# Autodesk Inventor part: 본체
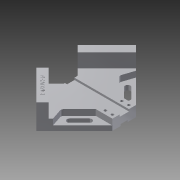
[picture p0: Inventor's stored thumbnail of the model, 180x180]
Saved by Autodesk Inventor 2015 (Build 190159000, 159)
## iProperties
Created: 2019-04
Part Number: 본체
Material: 알루미늄 6061
Document SubType Name: Modeling
Designer: LINEART-SSD.D4.16.04
Density: 2.7 g/cm^3
Appearance: 알루미늄 - 평지
Mass: 608.093 g
Surface Area: 428.235 cm^2
Volume: 225.22 cm^3
Author: LINEART-SSD.D4.16.04
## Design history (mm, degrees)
sketch "스케치1"
  geometry: L1 (-84.853, 0)-(0, -84.853); L2 (0, -84.853)-(84.853, 0); L3 (84.853, 0)-(0, 84.853); L4 (0, 84.853)-(-84.853, 0); L5 (-84.853, 0)-(84.853, 0); L6 (0, -84.853)-(0, 84.853); L7 (-84.853, 0)-(35.147, 0); 1 further point
  constraints: 14 end point, 2 midpoint, 2 parallel, 1 equal length, 1 horizontal, 1 perpendicular
  dimensions: "d0" = 120 distance of L1.start L1.end; "d1" = 45 deg angle of L1 L7; "d2" = 120 distance of L2.end L1.end
extrude "돌출1" new body sketch "스케치1" distance "d3" = 42; taper "d4" = 0 deg
sketch "스케치2"
  geometry: L1 (-84.853, 0)-(0, 84.853); L2 (84.853, 0)-(0, 84.853) reference; L3 (-74.246, -10.607)-(0, 63.64); L4 (0, 63.64)-(74.246, -10.607); L5 (-74.246, -10.607)-(0, -84.853); L6 (-84.853, 0)-(0, -84.853) reference; L7 (0, -84.853)-(74.246, -10.607); 1 further point
  constraints: 10 end point, 3 perpendicular, 1 collinear, 1 other
  dimensions: "d5" = 15 distance between parallel lines of L1 L3
extrude "돌출2" cut sketch "스케치2" distance "d6" = 24; taper "d7" = 0 deg
sketch "스케치3"
  geometry: L1 (0, 84.853)-(-35.355, 49.497); L2 (0, 84.853)-(-84.853, 0) reference; L3 (0, 84.853)-(35.355, 49.497); L4 (84.853, 0)-(0, 84.853) reference; L5 (35.355, 49.497)-(15.47, 29.612); L6 (-11.322, 29.612)-(-33.281, 51.571); L7 (0, -84.853)-(14, -84.853); L8 (0, -64.853)-(14, -64.853); L9 (4.143, 28.147)-(11.934, 28.147); L10 (4.143, 28.147)-(-7.786, 28.147); A1 r 5 centre (-7.786, 33.147) between (-11.322, 29.612) and (-7.786, 28.147); A2 r 5 centre (11.934, 33.147) between (11.934, 28.147) and (15.47, 29.612); 4 further points
  constraints: 16 end point, 9 point on line, 4 point on circle, 4 tangent, 2 centre point, 2 horizontal, 2 parallel, 1 equal radius, 1 perpendicular
  dimensions: "d8" = 50 distance of L1.start L1.end; "d9" = 50 distance of L1.start L3.end; "d12" = 14 distance of L7.start L7.end; "d13" = 20 distance between parallel lines of L7 L8; "d14" = 93 distance between parallel lines of L8 L9; "d16" = 33.12691 distance of point (-9.857, 28.147) L6.end; "d17" = 30.19387 distance of L3.end point (14.005, 28.147); "d18" = 14 distance of L9.start point (-9.857, 28.147); "d19" = 9.85711 distance of L9.start point (14, 28.147); "d20" = 5 radius of A1
extrude "돌출3" cut sketch "스케치3" stored distance "d21" = 0; taper "d22" = 0 deg
sketch "스케치4"
  geometry: L1 (0, -84.853)-(25, -84.853); L2 (-11, -64.853)-(25, -64.853); L3 (-11, -64.853)-(-25, -64.853); L4 (25, -64.853)-(25, -84.853); L5 (0, -84.853)-(-25, -84.853); L6 (-25, -84.853)-(-25, -64.853); 1 further point
  constraints: 12 end point, 3 horizontal, 1 parallel, 1 perpendicular, 1 vertical
  dimensions: "d23" = 25 distance of L1.start L1.end; "d24" = 20 distance between parallel lines of L1 L2; "d25" = 14 distance of L2.start L3.end; "d28" = 25 distance of L1.start L5.end
extrude "돌출4" cut sketch "스케치4" stored distance "d29" = 24; taper "d30" = 0 deg
sketch "스케치6"
  geometry: L1 (-7.786, 28.147)-(8.214, 28.147); L2 (11.934, 28.147)-(-7.786, 28.147) reference; L3 (-7.786, 28.147)-(-7.786, -64.853); L4 (8.214, 28.147)-(8.214, -64.853); L5 (-7.786, -64.853)-(8.214, -64.853); L6 (-20, -64.853)-(20, -64.853) reference; 1 further point
  constraints: 8 end point, 1 collinear, 1 point on line, 1 vertical
  dimensions: "d39" = 16 distance of L1.start L1.end; "d95" = 93 distance of L4.end L1.end; "d96" = 16 distance of L4.end L3.end
extrude "돌출5" cut sketch "스케치6" distance "d43" = 3.5; taper "d44" = 0 deg
sketch "스케치7"
  geometry: L1 (8.214, 64.853)-(-7.786, 64.853) reference; L2 (-6, -28.147)-(-6, 64.853); L3 (-6, 64.853)-(6, 64.853); L4 (6, 64.853)-(6, -28.147); L5 (6, -28.147)-(-7.343, -28.147); L6 (-7.786, -28.147)-(11.934, -28.147) reference; 2 further points
  constraints: 8 end point, 4 point on line, 1 parallel
  dimensions: "d47" = 12 distance of L2.end L3.end; "d48" = 93 distance of L2.start L2.end; "d49" = 93 distance of L3.end L4.end; "d50" = 13.34265 distance of L4.end L5.end; "d51" = 6 distance from line of L4 point (0, 0)
extrude "돌출6" cut sketch "스케치7" distance "d52" = 3; taper "d53" = 0 deg
sketch "스케치8"
  geometry: L1 (-84.853, 0)-(-70.711, -14.142); L2 (-84.853, 0)-(-20, -64.853) reference; L3 (-20, -64.853)-(-20, -36.569); L4 (-47.312, -9.256)-(-20, -36.569) reference; L5 (-70.711, -14.142)-(-20, -64.853); L6 (-84.853, 0)-(-77.782, 7.071); L7 (-33.281, 51.571)-(-84.853, 0) reference; L8 (-77.782, 7.071)-(-49.497, -21.213); L9 (-77.782, 7.071)-(-37.782, 7.071); L10 (-49.497, -21.213)-(-32.527, -38.184); L11 (-6, -64.853)-(6, -64.853) reference; L12 (0, -64.853)-(0, 0); L13 (20, -64.853)-(20, -36.569); L14 (70.711, -14.142)-(20, -64.853); L15 (-84.853, 0)-(-63.64, -21.213); L16 (-70.711, -14.142)-(-52.429, -8.048); L17 (70.711, -14.142)-(52.429, -8.048); L18 (20, -36.569)-(47.312, -9.256); A1 r 5 centre (-50.848, -12.792) between (-47.312, -9.256) and (-52.429, -8.048); A2 r 5 centre (50.848, -12.792) between (52.429, -8.048) and (47.312, -9.256); 3 further points
  constraints: 32 end point, 8 symmetric about line, 4 point on circle, 3 point on line, 2 centre point, 2 midpoint, 2 tangent, 2 vertical, 1 collinear, 1 equal length, 1 horizontal, 1 parallel, 2 other
  dimensions: "d54" = 20 distance of L1.start L1.end; "d57" = 10 distance of L1.start L6.end; "d58" = 40 distance of L6.end L8.end; "d59" = 45 deg angle of L8 L9; "d60" = 24 distance of L8.end L10.end; "d64" = 30 distance of L1.start L15.end; "d65" = 5 radius of A1; "d66" = 19.27051 distance of L1.end L16.end
extrude "돌출7" cut sketch "스케치8" distance "d62" = 10; taper "d63" = 0 deg
sketch "스케치10"
  geometry: L1 (-84.853, 0)-(-77.782, 7.071); L2 (-33.281, 51.571)-(-84.853, 0) reference; L3 (-84.853, 0)-(-74.853, 0); L4 (-77.782, 7.071)-(-49.497, -21.213); L5 (-77.782, 7.071)-(-37.782, 7.071); L6 (-49.497, -21.213)-(-32.527, -38.184); L7 (-52.679, -24.395)-(-35.709, -41.366); L8 (-29.345, -35.002)-(-46.315, -18.031); L9 (8.214, -64.853)-(-7.786, -64.853) reference; L10 (0.107, -64.853)-(0.107, 28.391); L11 (29.559, -35.002)-(46.529, -18.031); L12 (52.893, -24.395)-(35.923, -41.366); L13 (49.711, -21.213)-(32.741, -38.184); A1 r 4.5 centre (-49.497, -21.213) between (-46.315, -18.031) and (-52.679, -24.395); A2 r 4.5 centre (-32.527, -38.184) between (-35.709, -41.366) and (-29.345, -35.002); A3 r 4.5 centre (49.711, -21.213) between (52.893, -24.395) and (46.529, -18.031); A4 r 4.5 centre (32.741, -38.184) between (29.559, -35.002) and (35.923, -41.366); 3 further points
  constraints: 26 end point, 8 point on circle, 6 symmetric about line, 4 centre point, 4 tangent, 2 equal length, 2 horizontal, 1 collinear, 1 midpoint, 1 parallel, 1 point on line, 1 vertical, 2 other
  dimensions: "d67" = 10 distance of L1.start L1.end; "d68" = 45 deg angle of L3 L1 (derived); "d69" = 40 distance of L1.end L4.end; "d70" = 45 deg angle of L4 L5; "d71" = 24 distance of L4.end L6.end; "d72" = 9 diameter of A2; "d73" = 16.97056 horizontal distance of L13.start L13.end
extrude "돌출8" cut sketch "스케치10" stored distance "d74" = 10; taper "d75" = 0 deg
sketch "스케치11"
  geometry: L1 (8.214, -64.853)-(-7.786, -64.853) reference; L2 (0.107, -64.853)-(14.107, -64.853); L3 (20, -64.853)-(6, -64.853) reference; L4 (14.107, -64.853)-(14.107, -58.853); L5 (14.107, -58.853)-(14.107, -46.853); L6 (8, 28.147)-(8, -64.853) reference; L7 (0.107, -64.853)-(0.107, -27.265); C1 r 2.25 at (14.107, -58.853); C2 r 2.25 at (14.107, -46.853); C3 r 2.25 at (-13.893, -46.853); C4 r 2.25 at (-13.893, -58.853); 1 further point
  constraints: 8 end point, 4 centre point, 3 point on line, 2 coincident, 2 symmetric about line, 1 perpendicular, 1 vertical, 2 other
  dimensions: "d76" = 14 distance of L2.start L2.end; "d77" = 6 distance of L2.end L4.end; "d78" = 12 distance of L4.end L5.end; "d79" = 4.5 diameter of C1; "d80" = 4.5 diameter of C2; "d84" = 37.58774 distance of L2.start L7.end
extrude "돌출9" cut sketch "스케치11" distance "d82" = 10; taper "d83" = 0 deg
sketch "스케치13"
  geometry: C1 r 2.25 at (0, 0) reference; C2 r 4 at (0, 0); C3 r 2.25 at (0, -12) reference; C4 r 4 at (0, -12); C5 r 2.25 at (28, 0) reference; C6 r 4 at (28, 0); C7 r 2.25 at (28, -12) reference; C8 r 4 at (28, -12); 1 further point
  constraints: 4 centre point, 4 coincident
  dimensions: "d85" = 8 diameter of C2; "d86" = 8 diameter of C4; "d87" = 8 diameter of C6; "d88" = 8 diameter of C8
extrude "돌출10" cut sketch "스케치13" stored distance "d89" = 10; taper "d90" = 0 deg
sketch "스케치14"
  geometry: L1 (-33.281, 51.571)-(-84.853, 0) reference; L2 (-59.067, 25.786)-(-53.764, 20.482); L3 (-59.067, 25.786)-(-51.567, 25.786); 2 further points
  constraints: 4 end point, 1 coincident, 1 equal length, 1 horizontal, 1 midpoint, 1 perpendicular, 1 other
  dimensions: "d91" = 7.5 distance of L2.start L2.end; "d92" = 45 deg angle of L2 L3 (derived)
feature "엠보싱1" sketch "스케치14" dims "d0" = 120, "d1" = 45 deg, "d2" = 120, "d93" = 0.5, "d94" = 0
node "솔리드1"
